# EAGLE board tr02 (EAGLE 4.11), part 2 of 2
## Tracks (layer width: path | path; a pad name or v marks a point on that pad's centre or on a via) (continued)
BAC02  (via drill 0.61) (continued)
  Bottom 0.127: B07.F1 226.68,48.09 226.05,48.73 226.05,53.18 225.41,53.81 225.41,66.51 227,68.1 227,76.35 225.73,77.62 225.73,115.72 226.68,116.67 A07.F1 | v304.15,48.73 304.79,49.37 304.79,64.29 305.42,64.92 305.42,81.11 304.79,81.75 304.79,117.94 305.1,118.26 | 305.1,118.26 306.06,119.21 306.06,119.85 A01.E1 | v260.65,117.63 263.51,120.48 263.51,132.55 268.27,137.31 305.1,137.31 305.1,118.26
BAC03
  Bottom 0.127: B01.H1 306.06,44.92 305.1,45.87 305.1,63.97 305.74,64.6 305.74,81.43 305.1,82.07 305.1,112.55 306.06,113.5 A01.H1
BAC04  (via drill 0.61)
  Top 0.127: 299.07,112.55 301.29,112.55 302.56,111.28 A01.J1 | 299.07,112.55 236.52,112.55 234.94,114.13 233.67,114.13 232.4,112.86 229.22,112.86 227.63,111.28 A07.J1 | B07.J1 227.63,40.79 229.22,39.2 232.4,39.2 235.25,36.35 243.51,36.35 244.14,36.98 273.99,36.98 274.62,36.35 300.02,36.35 302.88,39.2 302.88,40.48 B01.J1 | v299.07,112.86 299.07,112.55
  Bottom 0.127: v299.07,112.86 298.75,113.18 298.75,114.45 299.71,115.4 301.61,115.4 301.61,43.02 302.88,41.74 B01.J1
BAC05  (via drill 0.61)
  Top 0.127: B07.L1 227.63,35.08 228.59,36.03 v262.24,36.03 301.61,36.03 302.56,35.08 B01.L1 | v229.86,104.93 227.63,104.93 A07.L1 | v230.81,116.99 232.4,118.58 v262.88,118.58 v304.15,118.58
  Bottom 0.127: v229.86,104.93 231.44,106.52 231.44,116.36 v230.81,116.99 | v304.15,118.58 304.47,118.26 304.47,106.2 303.51,105.24 A01.L1 | v262.24,36.03 261.92,36.35 261.92,80.8 263.51,82.38 263.51,117.94 v262.88,118.58
BAC06  (via drill 0.61)
  Top 0.127: 222.55,33.17 222.55,31.27 223.51,30.32 224.78,30.32 226.36,28.73 B07.N1 | 222.55,33.17 297.48,33.17 298.12,33.81 302.56,33.81 304.47,31.9 305.74,31.9 B01.M1 | v221.6,95.08 222.87,96.35 224.78,96.35 226.36,97.94 A07.N1 227.63,98.58 228.59,99.53 241.92,99.53 v242.56,98.89 | 222.55,33.17 v221.28,33.17 | v247.64,103.97 249.54,105.88 290.81,105.88 291.45,105.24 293.67,105.24 294.31,105.88 306.06,105.88 306.06,102.07 A01.M1
  Bottom 0.127: v221.6,95.08 222.24,94.45 222.24,57.62 220.65,56.03 220.65,55.4 221.92,54.13 221.92,33.81 v221.28,33.17 | v242.56,98.89 v247.64,103.97
BAC07  (via drill 0.61)
  Top 0.127: 249.86,23.65 304.47,23.65 305.74,24.92 B01.P1 | 249.86,23.65 228.9,23.65 227.63,22.38 B07.R1 | v227.32,89.37 227.95,90 243.51,90 | v245.1,88.42 243.51,90 | v249.86,23.01 249.86,23.65 | v262.56,97.31 262.88,96.99 304.15,96.99 305.74,95.4 A01.P1 | v260.34,86.19 259.38,87.15 254.3,87.15 251.45,90 243.51,90
  Bottom 0.127: v227.32,89.37 227.32,91.27 A07.R1 | v245.1,88.42 244.46,87.78 244.46,36.03 249.86,30.63 v249.86,23.01 | v262.56,97.31 260.34,95.08 v260.34,86.19
BAC08  (via drill 0.61)
  Top 0.127: B01.S1 305.74,18.57 304.15,16.98 299.71,16.98 290.81,8.09 228.59,8.09 227.63,9.04 B07.V1 | v303.83,89.69 305.1,89.69 305.74,89.05 A01.S1
  Bottom 0.127: B07.V1 227.32,10 228.27,10.95 228.27,77.62 227.32,78.57 A07.V1 | v303.83,89.69 304.47,89.05 304.47,50.32 301.93,47.78 301.93,43.97 304.47,41.43 304.47,21.11 306.06,19.52 B01.S1
BAC09  (via drill 0.61)
  Top 0.127: B07.E2 224.14,51.27 224.14,55.08 230.49,55.08 233.03,52.54 295.26,52.54 296.21,53.49 B01.D2 | v224.46,117.31 226.05,115.72 303.2,115.72 305.1,117.63 305.1,119.53 300.66,119.53 300.34,119.21 299.71,119.21 297.17,121.75 297.17,123.02 A01.D2
  Bottom 0.127: v224.46,117.31 224.46,119.53 224.14,119.85 A07.E2 | B01.D2 297.17,54.45 298.12,55.4 298.12,122.07 297.17,123.02 A01.D2
BAC10  (via drill 0.61)
  Top 0.127: v225.09,51.91 298.44,51.91 299.39,50.95 B01.E2 | A01.E2 300.66,120.17 300.98,119.85 305.42,119.85 305.42,115.4 264.78,115.4 262.24,112.86 239.38,112.86 236.84,115.4 225.41,115.4 224.46,114.45 A07.H2
  Bottom 0.127: B07.H2 224.14,44.92 225.09,45.87 v225.09,51.91 225.09,112.55 224.14,113.5 A07.H2
BAC11  (via drill 0.61)
  Top 0.127: v299.39,35.08 298.75,35.08 297.17,33.49 224.14,33.49 224.14,37.3 B07.K2
  Bottom 0.127: B07.K2 223.51,38.57 222.55,39.52 222.55,106.2 223.51,107.15 A07.K2 | 301.29,45.87 300.34,44.92 B01.H2 | 301.29,45.87 301.29,112.55 300.34,113.5 A01.H2 | v299.39,35.08 301.29,36.98 301.29,45.87
BIOP1  (via drill 0.61)
  Top 0.127: v237.79,39.2 298.44,39.2 299.39,38.25 B01.K2
  Bottom 0.127: B06.P2 236.84,25.87 237.79,26.82 v237.79,39.2 237.79,93.5 236.84,94.45 A06.P2 | B01.K2 299.71,38.57 298.75,39.52 298.75,101.75 300.02,103.02 300.02,107.15 A01.K2
BIOP2  (via drill 0.61)
  Top 0.127: B01.M2 299.39,31.27 297.8,29.68 293.36,29.68 290.18,26.51 233.03,26.51 230.49,23.96 227.32,23.96 225.73,22.38 225.73,21.11 226.36,21.11 226.68,20.79 231.76,20.79 232.71,21.74 B06.R2 | v247.64,97.31 247.95,96.99 259.06,96.99 261.61,99.53 297.8,99.53 299.39,101.12 A01.M2 | v246.37,93.5 247.32,92.54 247.32,90.64 234.94,90.64 233.98,91.59 A06.R2
  Bottom 0.127: B06.R2 233.03,22.7 232.08,23.65 232.08,62.06 233.35,63.34 233.35,77.62 232.08,78.89 232.08,90.32 233.03,91.27 A06.R2 | v247.64,97.31 246.37,96.04 v246.37,93.5
BIOP4  (via drill 0.61)
  Top 0.127: A06.S2 237.16,88.42 238.43,87.15 v239.7,87.15 240.02,87.46 251.45,87.46 v252.08,88.1 | v253.67,89.69 254.3,90.32 271.45,90.32 272.08,90.96 277.16,90.96 277.48,90.64 285.42,90.64 285.42,94.77 287,96.35 298.44,96.35 299.39,95.4 A01.P2
  Bottom 0.127: 240.97,7.14 301.29,7.14 301.29,23.65 300.34,24.6 B01.P2 | 240.97,7.14 240.33,7.14 235.25,12.22 235.25,17.3 236.21,18.25 B06.S2 | v239.7,87.15 240.97,85.88 240.97,51.59 239.7,50.32 239.7,49.05 240.97,47.78 240.97,7.14 | v252.08,88.1 v253.67,89.69
BMB00H
  Bottom 0.127: B02.B1 290.81,60.8 291.77,61.75 291.77,128.42 290.81,129.38 A02.B1
BMB01H  (via drill 0.61)
  Top 0.127: v290.18,58.57 v281.29,67.46 | v281.29,78.57 283.51,80.8 v284.47,80.8 | v282.88,119.53 286.69,123.34 289.86,123.34 A02.D1
  Bottom 0.127: v290.18,58.57 290.18,54.45 B02.D1 | v281.29,67.46 v281.29,78.57 | v284.47,80.8 282.88,82.38 v282.88,119.53
BMB02H  (via drill 0.61)
  Top 0.127: v260.34,50.63 261.61,49.37 292.09,49.37 293.04,50.32 B02.E1 | v255.57,128.42 v271.76,128.42
  Bottom 0.127: v260.34,50.63 257.16,53.81 257.16,110.96 254.3,113.82 254.3,127.15 v255.57,128.42 | v271.76,128.42 278.12,134.77 292.4,134.77 292.4,122.07 293.36,121.12 A02.E1
BMB03H  (via drill 0.61)
  Top 0.127: 238.75,55.4 236.52,55.4 235.89,56.03 235.25,56.03 233.67,54.45 B06.D2 | 238.75,55.4 v291.13,55.4 | 238.75,55.4 v238.75,56.03 | v288.91,132.55 288.28,131.92 241.29,131.92 v240.65,132.55
  Bottom 0.127: v291.13,55.4 291.77,54.76 291.77,42.7 290.81,41.74 B02.J1 | 237.79,128.11 235.25,128.11 233.98,126.83 233.98,124.61 233.67,124.29 A06.D2 | 237.79,128.11 237.79,105.24 237.16,104.61 237.16,103.66 238.11,102.7 238.11,56.67 v238.75,56.03 | v288.91,132.55 288.91,112.86 290.18,111.59 A02.J1 | v240.65,132.55 237.79,129.69 237.79,128.11
BMB03L
  Bottom 0.127: B02.H1 293.36,44.92 292.4,45.87 292.4,77.3 293.67,78.57 293.67,80.8 292.4,82.07 292.4,112.55 293.36,113.5 A02.H1
BMB04H  (via drill 0.61)
  Top 0.127: v240.65,50 237.48,50 237.16,50.32 B06.E2 | v241.29,120.48 237.16,120.48 A06.E2 | v248.91,30.32 292.09,30.32 293.04,31.27 B02.M1 | v247,106.2 v293.36,106.2
  Bottom 0.127: 241.29,50.63 v240.65,50 | 241.29,117.31 v241.29,120.48 | 241.29,50.63 241.29,117.31 | v248.91,30.32 241.29,37.94 241.29,50.63 | v293.36,106.2 293.36,102.07 A02.M1 | v247,106.2 244.14,109.05 244.14,114.45 241.29,117.31
BMB04L
  Bottom 0.127: B02.L1 290.18,35.4 289.23,36.35 289.23,103.02 290.18,103.97 A02.L1
BMB05H  (via drill 0.61)
  Top 0.127: v287.96,41.11 280.34,48.73 234.94,48.73 233.98,47.78 B06.F2 | v233.98,113.18 234.94,112.23 288.91,112.23 | 288.91,112.23 290.81,112.23 v293.67,109.37 | v295.9,89.37 295.58,89.05 294.31,89.05 A02.S1 | v288.91,111.59 288.91,112.23
  Bottom 0.127: B02.S1 293.36,19.52 293.36,20.79 288.91,25.23 288.91,40.16 v287.96,41.11 288.28,41.43 288.91,42.06 v288.91,111.59 | v233.98,113.18 233.98,116.36 233.67,116.67 A06.F2 | v293.67,109.37 295.58,107.47 295.58,89.69 v295.9,89.37
BMB05L
  Bottom 0.127: B02.P1 293.99,25.87 294.94,26.82 294.94,93.5 293.99,94.45 A02.P1
BMB06H  (via drill 0.61)
  Top 0.127: v286.69,41.11 281.61,46.19 267.64,46.19 v266.05,47.78 | v266.05,56.35 266.37,56.67 v272.4,56.67
  Bottom 0.127: v286.69,41.11 286.05,41.74 286.05,49.05 287,50 B02.E2 | v266.05,47.78 v266.05,56.35 | v272.4,56.67 273.04,57.3 273.04,117.31 276.21,120.48 276.21,131.6 279.7,131.6 279.7,126.52 280.97,125.25 287,125.25 287,121.12 A02.E2
BMB06L  (via drill 0.61)
  Top 0.127: v235.57,55.08 282.56,55.08 283.51,54.13 B02.D2
  Bottom 0.127: 235.25,55.08 235.25,78.89 236.52,80.16 236.52,80.8 235.25,82.07 235.25,112.55 236.21,113.5 A06.H2 | 235.25,55.08 235.25,45.87 236.21,44.92 B06.H2 | B02.D2 284.47,54.45 285.42,55.4 285.42,122.07 284.47,123.02 A02.D2 | 235.25,55.08 v235.57,55.08
BMB07H
  Bottom 0.127: B02.K2 287,38.57 285.74,39.84 285.74,52.22 286.05,52.54 286.05,106.2 287,107.15 A02.K2
BMB07L
  Top 0.127: B06.J2 233.98,40.79 234.62,40.16 239.06,40.16 239.38,39.84 287.96,39.84 288.91,40.79 288.91,43.65 287.64,43.65 B02.H2
  Bottom 0.127: A06.J2 233.67,110.32 234.62,109.37 234.62,42.7 233.67,41.74 B06.J2 | A02.H2 287.64,113.5 287.96,113.18 287.96,108.74 288.59,108.1 288.59,45.87 287.64,44.92 B02.H2
BMB08H  (via drill 0.61)
  Top 0.127: v234.94,25.23 236.21,23.96 254.94,23.96 255.57,24.6 273.67,24.6 274.31,23.96 285.74,23.96 286.69,24.92 B02.P2 287.96,25.55 290.5,25.55 v292.09,27.14 | v291.45,57.94 291.77,57.94 291.77,70 304.47,82.7 304.47,87.78 301.61,90.64 287.64,90.64 287.64,94.45 A02.P2
  Bottom 0.127: v234.94,25.23 234.94,36.03 236.21,37.3 B06.K2 | v291.45,57.94 292.09,57.3 v292.09,27.14
BMB08L  (via drill 0.61)
  Top 0.127: v298.44,32.86 288.91,32.86 287.96,31.9 B02.M2 | v299.07,103.34 298.44,102.7 288.91,102.7 287.96,101.75 A02.M2 286.69,101.12 285.42,99.85 259.38,99.85 259.06,100.16 239.38,100.16 v236.52,103.02
  Bottom 0.127: v298.44,32.86 298.44,102.7 v299.07,103.34 | v236.52,103.02 236.52,107.15 A06.K2
BMB09H  (via drill 0.61)
  Top 0.127: v285.42,27.46 285.1,27.14 256.84,27.14 | 256.84,27.14 229.86,27.14 225.73,31.27 224.46,31.27 B07.M2 | v287,86.51 284.47,83.97 v256.21,83.97 | 256.84,27.14 v256.84,27.46 | v255.57,103.02 238.11,103.02 237.16,103.97 236.21,103.97 234.94,102.7 229.86,102.7 228.9,101.75 224.46,101.75 A07.M2
  Bottom 0.127: v285.42,27.46 285.42,21.11 287,19.52 B02.S2 | v287,86.51 287,88.1 A02.S2 | 256.84,83.34 v256.21,83.97 | v256.84,27.46 256.84,83.34 | v255.57,103.02 256.84,101.75 256.84,83.34
BMB10H  (via drill 0.61)
  Top 0.127: v225.73,19.2 227.32,17.62 230.81,17.62 231.12,17.93 235.89,17.93 236.52,17.3 282.24,17.3 283.51,16.03 B02.T2 | 251.76,90.32 253.99,88.1 254.62,88.1 255.26,87.46 257.8,87.46 258.43,88.1 259.7,88.1 260.97,86.83 282.56,86.83 283.51,85.88 A02.T2 | 251.76,90.32 247.64,94.45 246.05,94.45 245.1,93.5 225.73,93.5 224.46,94.77 A07.P2 | v219.06,87.78 221.6,90.32 251.76,90.32
  Bottom 0.127: v225.73,19.2 225.73,20.79 | 225.73,20.79 225.73,23.01 224.14,24.6 B07.P2 | 225.73,20.79 219.06,20.79 v219.06,87.78
BMB11H  (via drill 0.61)
  Top 0.127: B07.S2 224.46,18.57 226.05,16.98 274.94,16.98 282.24,9.68 283.51,9.68 B02.V2 | v231.12,87.15 225.73,87.15 224.46,88.42 A07.S2 | v231.76,73.18 232.4,73.81 288.28,73.81 293.67,79.21 293.67,80.48 285.74,80.48 284.78,79.53 A02.V2
  Bottom 0.127: A02.V2 283.83,78.57 282.88,77.62 282.88,10.95 283.83,10 B02.V2 | v231.12,87.15 231.76,86.51 v231.76,73.18
CLEAR_AC_L  (via drill 0.61)
  Top 0.127: v270.5,25.55 273.99,25.55 B03.P2 | v269.23,91.27 272.72,94.77 273.99,94.77 A03.P2 | v267.64,122.07 254.3,122.07 253.03,123.34 A05.D1
  Bottom 0.127: v270.5,25.55 269.86,26.19 269.86,90.64 | 269.86,90.64 v269.23,91.27 | v267.64,122.07 267,121.44 267,104.29 269.86,101.43 269.86,90.64
GND  (via drill 0.61)  (1 unrouted)
  Top 0.203: C3.2 148.26,167.16 145.08,167.16 140,162.08 R4.1 138.73,162.08 137.46,160.81 133.65,160.81 131.11,158.27 S4.2 | B03.R2 272.08,21.74 277.16,21.74 B03.R1 278.43,21.74 283.51,21.74 B02.R2 | B03.F1 277.16,47.14 272.08,47.14 B03.F2 | B02.N1 289.86,28.41 284.78,28.41 B02.N2 | B02.F2 284.78,47.14 289.86,47.14 B02.F1 291.13,47.14 296.21,47.14 B01.F2 | B02.K1 293.04,37.62 292.09,36.66 282.56,36.66 281.61,37.62 B03.K1 | B03.C1 280.34,56.67 275.26,56.67 B03.C2 273.99,57.3 273.04,58.26 234.94,58.26 | B03.A1 280.66,62.7 280.66,57.62 B03.C1 | B03.C1 281.61,56.67 286.69,56.67 B02.C2 287.96,56.67 293.04,56.67 B02.C1 | B02.A1 293.36,62.7 293.36,57.62 B02.C1 | B02.C1 294.31,56.67 299.39,56.67 B01.C2 300.66,56.67 304.47,56.67 | 304.47,56.67 305.74,56.67 B01.C1 306.06,57.62 306.06,62.7 B01.A1 | B01.U2 300.66,12.85 302.88,15.08 B01.T1 | B02.U2 287.96,12.85 290.18,15.08 B02.T1 | B01.R2 296.21,21.74 291.13,21.74 B02.R1 | 296.53,42.38 296.53,41.74 B01.J2 | 296.53,42.38 296.53,46.83 B01.F2 | 301.29,47.14 297.48,47.14 B01.F2 | 301.29,47.14 302.56,47.14 B01.F1 | 296.53,42.38 306.06,42.38 306.06,38.57 B01.K1 | B01.N1 302.56,28.09 297.48,28.09 B01.N2 | 304.47,56.67 304.47,49.68 303.83,49.68 301.29,47.14 | B18.T1 87.93,15.39 88.89,14.44 123.81,14.44 124.76,15.39 B15.T1 126.03,15.39 126.98,14.44 177.79,14.44 | 177.79,14.44 176.83,15.39 B11.T1 | 200.01,14.44 177.79,14.44 | 200.01,14.44 200.96,15.39 B09.T1 | 212.71,14.44 213.66,15.39 B08.T1 | 212.71,14.44 200.01,14.44 | 225.41,14.44 226.36,15.39 B07.T1 | 225.41,14.44 212.71,14.44 | 238.11,14.44 239.06,15.39 B06.T1 | 238.11,14.44 225.41,14.44 | 238.11,14.44 272.4,14.44 273.99,12.85 B03.U2
  Top 0.203: 57.13,125.56 47.61,125.56 46.66,126.52 A21.C2 45.39,127.15 44.44,128.11 34.91,128.11 33.96,127.15 A22.C2 32.69,126.52 27.61,126.52 A23.C1 26.34,126.52 21.26,126.52 A23.C2 19.99,126.52 14.91,126.52 A24.C1 13.64,126.52 8.56,126.52 A24.C2 | 57.13,125.56 58.09,126.52 A20.C2 | 69.83,125.56 70.79,126.52 A19.C2 | 69.83,125.56 57.13,125.56 | 82.53,125.56 83.49,126.52 A18.C2 | 82.53,125.56 69.83,125.56 | 95.23,125.56 96.19,126.52 A17.C2 | 95.23,125.56 82.53,125.56 | 107.94,125.56 108.89,126.52 A16.C2 | 107.94,125.56 95.23,125.56 | 120.64,125.56 121.59,126.52 A15.C2 | 120.64,125.56 107.94,125.56 | 120.64,125.56 133.34,125.56 134.29,126.52 A14.C2 135.56,126.52 140.64,126.52 A14.C1 141.91,126.83 146.99,126.83 A13.C2 148.26,126.52 149.53,125.25 158.42,125.25 159.69,126.52 A12.C2 160.96,126.52 161.91,125.56 171.44,125.56 | B24.C2 8.56,56.67 13.64,56.67 B24.C1 14.91,56.67 19.99,56.67 B23.C2 21.26,56.67 26.34,56.67 B23.C1 | 15.86,36.03 16.81,35.08 B23.L2 | 15.86,36.03 14.59,37.3 B24.K1 14.91,38.25 17.13,40.48 B23.J2 | B23.F1 23.16,47.14 18.08,47.14 B23.F2 | 15.86,36.03 24.75,36.03 26.34,37.62 B23.K1 | B23.U2 21.26,12.85 23.48,15.08 B23.T1 23.48,16.35 23.48,21.43 B23.R1 | B24.U2 8.56,12.85 10.78,15.08 B24.T1 10.78,16.35 10.78,21.43 B24.R1 | B24.R2 5.38,21.74 10.46,21.74 B24.R1 | B24.N2 4.43,29.05 4.43,34.12 B24.L2 4.43,35.4 4.43,40.48 B24.J2 | B23.R2 16.81,21.74 11.73,21.74 B24.R1 | B24.F1 10.46,47.14 5.38,47.14 B24.F2 | B23.N1 23.16,28.09 18.08,28.09 B23.N2 | 22.53,83.97 23.48,84.92 A23.T1 | 22.53,83.97 21.26,82.7 A23.U2 | 22.53,83.97 v34.59,83.97 34.91,83.97 47.29,83.97 47.61,84.29
  Top 0.203: 47.61,84.29 48.56,85.24 A21.T1 | 47.61,84.29 60.31,84.29 61.26,85.24 A20.T1 | A24.U2 8.56,82.7 10.78,84.92 A24.T1 | A23.R2 16.81,91.59 11.73,91.59 A24.R1 10.46,91.59 5.38,91.59 A24.R2 4.43,92.54 4.43,97.62 A24.N2 | A24.J2 4.43,111.59 4.43,116.67 A24.F2 5.38,116.99 10.46,116.99 A24.F1 | A23.F1 23.16,116.99 18.08,116.99 A23.F2 | A23.N1 23.16,97.94 18.08,97.94 A23.N2 | 85.71,84.29 76.19,84.29 75.23,85.24 A19.T1 | 85.71,84.29 86.66,85.24 A18.T1 | 98.41,84.29 99.36,85.24 A17.T1 | 98.41,84.29 85.71,84.29 | 98.41,84.29 111.11,84.29 112.06,85.24 A16.T1 113.33,85.24 114.28,84.29 120.95,84.29 122.22,85.56 124.76,85.56 A15.T1 126.03,85.24 131.11,85.24 A14.T2 132.38,85.24 137.46,85.24 A14.T1 138.73,85.24 139.69,84.29 149.21,84.29 | 149.21,84.29 150.16,85.24 A13.T1 | 161.91,84.29 162.86,85.24 A12.T1 | 161.91,84.29 149.21,84.29 | 174.61,84.29 175.56,85.24 A11.T1 | 174.61,84.29 161.91,84.29 | 174.61,84.29 187.31,84.29 188.26,85.24 A10.T1 189.53,85.88 190.49,86.83 200.01,86.83 200.96,85.88 A09.T1 202.23,85.88 203.5,87.15 209.22,87.15 210.49,85.88 213.66,85.88 A08.T1 214.93,85.88 215.89,86.83 225.41,86.83 226.36,85.88 A07.T1 227.63,85.88 227.95,86.19 232.08,86.19 232.71,86.83 238.11,86.83 239.06,85.88 A06.T1 240.33,85.88 241.29,86.83 250.81,86.83 251.76,85.88 A05.T1 253.03,85.24 258.11,85.24 A04.T2 259.38,85.24 264.46,85.24 A04.T1 | 171.44,125.56 172.39,126.52 A11.C2 | 184.14,125.56 185.09,126.52 A10.C2 | 171.44,125.56 184.14,125.56 | 184.14,125.56 196.84,125.56 197.79,126.52 A09.C2 199.06,127.15 200.01,128.11 209.54,128.11 210.49,127.15 A08.C2 211.76,126.52 213.66,126.52 214.62,125.56 222.24,125.56
  Top 0.203: 222.24,125.56 223.19,126.52 A07.C2 | 235.57,125.56 236.21,126.2 A06.C2 | 222.24,125.56 235.57,125.56 | 235.57,125.56 247.64,125.56 248.59,126.52 A05.C2 249.86,127.15 252.08,129.38 A05.B1 252.72,129.38 254.94,127.15 A05.C1 256.21,126.52 261.29,126.52 A04.C2 262.56,126.52 263.51,125.56 273.04,125.56 273.99,126.52 A03.C2 275.26,126.52 280.34,126.52 A03.C1 281.61,126.52 286.69,126.52 A02.C2 287.96,126.52 293.04,126.52 A02.C1 294.31,126.52 299.39,126.52 A01.C2 300.66,126.52 305.74,126.52 A01.C1 306.06,127.47 306.06,132.55 A01.A1 | A03.K1 281.61,107.47 282.56,106.52 292.09,106.52 293.04,107.47 A02.K1 294.31,108.1 295.9,109.69 | 295.9,109.69 296.53,110.32 A01.J2 | A01.F1 302.56,116.99 297.48,116.99 A01.F2 296.21,116.99 291.13,116.99 A02.F1 289.86,116.99 284.78,116.99 A02.F2 | 295.9,109.69 304.15,109.69 305.74,108.1 A01.K1 | A03.R2 272.08,91.59 277.16,91.59 A03.R1 278.43,91.59 283.51,91.59 A02.R2 | A03.F1 277.16,116.99 272.08,116.99 A03.F2 | 234.94,58.26 225.41,58.26 224.46,57.3 B07.C2 223.19,57.3 222.24,58.26 214.62,58.26 213.35,56.98 211.76,56.98 B08.C2 210.49,57.3 209.54,58.26 196.84,58.26 | 234.94,58.26 235.89,57.3 B06.C2 | 196.84,58.26 174.61,58.26 173.66,57.3 B11.C2 | 196.84,58.26 197.79,57.3 B09.C2 | A05.V1 253.03,79.53 255.26,81.75 A05.U1 256.21,82.7 257.16,83.65 266.69,83.65 267.64,82.7 A04.U1 268.91,82.07 273.99,82.07 A03.U2 275.26,82.7 276.21,83.65 288.91,83.65 | A01.U2 300.66,82.7 302.88,84.92 A01.T1 | 288.91,83.65 290.18,84.92 A02.T1 | 288.91,83.65 287.96,82.7 A02.U2 | A01.R2 296.21,91.59 291.13,91.59 A02.R1 | A01.N1 302.56,97.94 297.48,97.94 A01.N2
  Bottom 0.203: S3.2 148.89,158.9 148.89,166.52 C3.2 | B03.U2 275.26,12.85 277.48,15.08 B03.T1 277.48,16.35 277.48,21.43 B03.R1 277.48,22.7 277.48,27.78 B03.N1 278.12,29.05 279.07,30 279.07,35.71 280.66,37.3 B03.K1 | B03.R2 271.45,22.7 271.45,27.78 B03.N2 271.13,29.05 271.13,34.12 B03.L2 271.13,35.4 271.13,40.48 B03.J2 271.13,41.74 271.13,46.83 B03.F2 | B02.R2 283.83,22.7 283.83,27.78 B02.N2 283.83,29.05 283.83,34.12 B02.L2 283.83,35.4 283.83,40.48 B02.J2 283.83,41.74 283.83,46.83 B02.F2 | B01.T1 302.88,16.35 302.88,21.43 B01.R1 302.88,22.7 302.88,27.78 B01.N1 | B02.R1 290.18,21.43 290.18,16.35 B02.T1 | B01.R2 296.53,22.7 296.53,27.78 B01.N2 296.53,29.05 296.53,34.12 B01.L2 296.53,35.4 296.53,40.48 B01.J2 | A14.M2 135.24,102.07 136.83,103.66 136.83,109.37 137.78,110.32 A14.J1 137.78,111.59 136.19,113.18 136.19,118.9 135.24,119.85 A14.E2 134.61,121.12 134.61,126.2 A14.C2 | B24.A1 13.96,62.7 13.96,57.62 B24.C1 13.96,56.35 12.37,54.76 12.37,49.05 11.41,48.09 B24.F1 | B23.C1 26.66,57.62 26.66,62.7 B23.A1 26.66,63.97 25.38,65.24 25.38,83.65 24.11,84.92 A23.T1 23.48,86.19 23.48,91.27 A23.R1 23.48,92.54 23.48,97.62 A23.N1 | B23.F2 17.13,46.83 17.13,41.74 B23.J2 | B23.N1 23.48,27.78 23.48,22.7 B23.R1 | B24.N2 4.43,27.78 4.43,22.7 B24.R2 | B24.N1 10.78,27.78 10.78,22.7 B24.R1 | B23.R2 17.13,22.7 17.13,27.78 B23.N2 17.13,29.05 17.13,34.12 B23.L2 | B24.F2 4.43,46.83 4.43,41.74 B24.J2 | v34.59,83.97 35.86,85.24 A22.T1 | A24.A1 13.96,132.55 13.96,127.47 A24.C1 | A23.A1 26.66,132.55 26.66,127.47 A23.C1 26.66,126.2 25.07,124.61 25.07,115.72 | 25.07,115.72 25.07,110.01 26.66,108.42 A23.K1
  Bottom 0.203: 25.07,115.72 24.11,116.67 A23.F1 | A24.K1 13.96,108.42 12.37,110.01 12.37,115.72 11.41,116.67 A24.F1 | A24.N1 10.78,97.62 10.78,92.54 A24.R1 10.78,91.27 10.78,86.19 A24.T1 | A23.R2 17.13,92.54 17.13,97.62 A23.N2 17.13,98.89 17.13,103.97 A23.L2 17.13,105.24 17.13,110.32 A23.J2 17.13,111.59 17.13,116.67 A23.F2 | A24.N2 4.43,98.89 4.43,103.97 A24.L2 4.43,105.24 4.43,110.32 A24.J2 | B15.C2 121.59,57.3 114.28,57.3 114.28,79.53 113.02,80.8 113.02,84.92 A16.T1 | B18.C2 84.44,57.62 86.03,59.21 86.03,83.97 86.98,84.92 A18.T1 | A14.P1 140.96,94.45 139.37,92.86 139.37,87.15 138.42,86.19 A14.T1 | A04.L2 258.43,105.24 257.48,106.2 257.48,111.91 255.89,113.5 A05.H1 255.89,114.77 256.84,115.72 256.84,125.25 255.89,126.2 A05.C1 | A03.A1 280.66,132.55 280.66,127.47 A03.C1 | A02.A1 293.36,132.55 293.36,127.47 A02.C1 293.99,126.2 295.58,124.61 295.58,118.9 296.53,117.94 A01.F2 296.53,116.67 296.53,111.59 A01.J2 296.53,110.32 296.53,105.24 A01.L2 296.53,103.97 296.53,98.89 A01.N2 296.53,97.62 296.53,92.54 A01.R2 | A03.T1 277.8,86.19 277.8,91.27 A03.R1 277.48,92.54 277.48,97.62 A03.N1 | A03.R2 271.13,92.54 271.13,97.62 A03.N2 271.13,98.89 271.13,103.97 A03.L2 271.13,105.24 271.13,110.32 A03.J2 271.13,111.59 271.13,116.67 A03.F2 | A02.R2 283.83,92.54 283.83,97.62 A02.N2 283.83,98.89 283.83,103.97 A02.L2 283.83,105.24 283.83,110.32 A02.J2 283.83,111.59 283.83,116.67 A02.F2 | A04.V1 264.78,79.84 264.78,84.92 A04.T1 | A05.U1 254.94,82.7 252.72,84.92 A05.T1 | A01.T1 302.88,86.19 302.88,91.27 A01.R1 302.88,92.54 302.88,97.62 A01.N1 | A02.T1 290.18,86.19 290.18,91.27 A02.R1 290.18,92.54 290.18,97.62 A02.N1
  Bottom 0.203: B08.C2 211.44,57.62 211.76,57.94 211.76,62.06 213.03,63.34 213.03,83.97 213.98,84.92 A08.T1
I_LINE
  Bottom 0.127: B03.V2 271.13,10 270.18,10.95 270.18,19.2 272.72,21.74 272.72,50.95 270.18,53.49 270.18,75.4 271.13,76.35 271.13,78.57 A03.V2
I_RUN  (via drill 0.61)
  Top 0.127: v267,59.21 280.34,72.54 292.09,72.54 298.75,79.21 298.75,87.46 300.34,87.46 301.29,88.42 301.29,90.32 278.43,90.32 277.16,89.05 275.26,89.05 A03.S2
  Bottom 0.127: v267,59.21 267,7.77 272.08,7.77 273.04,8.73 273.04,16.98 274.31,18.25 B03.S2
I_TS1  (via drill 0.61)
  Top 0.127: v264.46,20.79 296.53,20.79 296.53,16.35 B01.T2 | v262.88,78.57 263.51,77.94 279.38,77.94 283.19,81.75 286.37,81.75 287,81.11 290.81,81.11 294.94,85.24 296.21,85.24 A01.T2
  Bottom 0.127: v264.46,20.79 263.19,22.06 263.19,78.26 v262.88,78.57
I_TS3  (via drill 0.61)
  Top 0.127: v265.1,72.22 266.37,73.49 289.23,73.49 298.44,82.7 298.44,88.42 299.39,88.42 A01.S2
  Bottom 0.127: v265.1,72.22 265.1,47.46 265.42,47.14 265.42,7.46 296.53,7.46 298.12,9.04 298.12,16.66 299.71,18.25 B01.S2
I_TT_INST  (via drill 0.61)
  Top 0.127: v268.59,84.92 268.91,85.24 270.81,85.24 A03.T2
  Bottom 0.127: v268.59,84.92 266.05,82.38 266.05,81.11 267.96,79.21 267.96,8.09 271.76,8.09 272.72,9.04 272.72,14.12 271.76,15.08 B03.T2
INITIALIZE  (via drill 0.61)
  Top 0.127: v243.51,71.27 265.42,71.27 267,72.86 290.18,72.86 296.21,78.89 A01.V2
  Bottom 0.127: B01.V2 296.53,10 295.58,10.95 295.58,77.62 296.53,78.57 A01.V2 | 244.14,71.27 244.14,96.04 241.6,98.58 241.6,112.55 242.56,113.5 A06.H1 | 244.14,71.27 244.14,45.87 243.19,44.92 B06.H1 | 244.14,71.27 v243.51,71.27
INT_REQ_L  (via drill 0.61)
  Top 0.127: v262.24,32.22 273.67,32.22 273.99,31.9 B03.M2 | v259.7,100.8 260.34,100.16 273.04,100.16 273.99,101.12 A03.M2
  Bottom 0.127: v262.24,32.22 261.29,33.17 261.29,76.35 259.06,78.57 A04.V2 258.43,79.84 257.48,80.8 257.48,98.58 v259.7,100.8
N$1
  Bottom 0.127: B07.C1 229.86,56.35 228.9,55.4 228.9,15.39 233.03,11.27 233.03,10 B06.V2
N$2
  Top 0.127: B11.S1 180.01,19.2 180.96,20.16 209.54,20.16 210.49,19.2 B08.S2
N$3
  Top 0.127: B11.C1 180.01,56.67 181.6,55.08 214.62,55.08 216.52,53.18 216.52,51.27 211.44,51.27 B08.E2
  Bottom 0.127: B08.E2 211.44,50 212.71,48.73 212.71,11.27 213.98,10 B08.V1
N$4  (via drill 0.61)
  Top 0.127: v95.55,111.91 95.87,111.59 99.05,111.59 99.68,112.23 113.02,112.23 v114.92,110.32
  Bottom 0.127: v95.55,111.91 95.55,121.44 93.97,123.02 A17.D2 | v114.92,110.32 114.28,109.69 114.28,103.34 115.55,102.07 A16.M1
N$5  (via drill 0.61)
  Top 0.127: v110.16,118.58 92.69,118.58 91.11,120.17 A18.E1
  Bottom 0.127: v110.16,118.58 111.11,117.63 111.11,106.52 112.38,105.24 A16.L1
N$6  (via drill 0.61)
  Top 0.127: v96.5,110.32 95.87,109.69 77.45,109.69 73.33,113.82 72.06,113.82 A19.H2 71.11,113.5 68.88,111.28 A19.J2
  Bottom 0.127: A19.K2 70.79,108.1 68.56,110.32 A19.J2 | v96.5,110.32 96.5,108.42 A17.K2
N$7  (via drill 0.61)
  Top 0.127: v235.57,80.48 234.94,80.48 233.98,79.53 A06.V2 | v234.94,126.52 230.81,126.52 A07.C1
  Bottom 0.127: v235.57,80.48 234.94,81.11 v234.94,126.52
N$8
  Top 0.127: A11.S1 180.01,89.05 180.96,90 209.54,90 210.49,89.05 A08.S2
N$9  (via drill 0.61)
  Top 0.127: v211.44,80.16 213.03,80.16 213.66,79.53 A08.V1 | v209.54,129.38 208.9,128.74 201.28,128.74 200.65,129.38 197.47,129.38 196.2,128.11 180.96,128.11 180.01,127.15 A11.C1
  Bottom 0.127: v211.44,80.16 209.85,81.75 209.85,116.67 211.12,117.94 211.12,119.85 A08.E2 210.81,121.12 210.81,124.29 209.85,125.25 209.85,129.06 v209.54,129.38
N$10  (1 unrouted)
N$11  (via drill 0.61)
  Top 0.127: v164.45,115.09 165.4,116.04 v168.9,116.04
  Bottom 0.127: v164.45,115.09 164.77,114.77 164.77,106.2 163.82,105.24 A12.L1 | v168.9,116.04 168.58,116.36 168.58,122.07 169.53,123.02 A11.D2
N$12  (via drill 0.61)
  Top 0.127: 87.93,106.52 83.17,106.52 v82.53,107.15 | 87.93,106.52 88.89,106.52 89.84,107.47 A18.K1 91.11,107.47 92.06,106.52 161.28,106.52 161.59,106.83 v161.91,107.15 165.72,107.15 166.04,107.47 A12.K1 | 87.93,106.52 v87.93,107.15 | v160.96,123.34 162.86,123.34 A12.D1 | v210.17,118.26 209.54,118.9 v163.5,118.9
  Bottom 0.127: 82.53,97.94 81.58,97.94 A18.N2 | 82.53,97.94 82.85,97.94 85.39,95.4 85.39,94.13 86.98,92.54 A18.R1 | v82.53,107.15 82.53,97.94 | v87.93,107.15 88.57,107.78 88.57,117.63 87.3,118.9 87.3,123.02 A18.D1 | 161.59,107.15 161.59,112.55 160.64,113.5 A12.H2 160.01,114.77 159.05,115.72 159.05,121.44 v160.96,123.34 | 161.59,107.15 161.59,94.13 163.18,92.54 A12.R1 | 161.59,107.15 v161.91,107.15 | v210.17,118.26 209.54,117.63 209.54,81.11 208.27,79.84 A08.V2 | v163.5,118.9 163.5,123.02 A12.D1
N$13  (1 unrouted)
N$14
  Top 0.127: A19.D2 68.56,123.02 70.79,120.8 A19.E2
N$15  (via drill 0.61)
  Top 0.127: v104.44,119.53 104.12,119.21 96.5,119.21 93.97,121.75 83.8,121.75 80.95,118.9 70.15,118.9 68.88,117.63 A19.F2 | v105.08,108.1 108.89,108.1 A16.K2
  Bottom 0.127: v104.44,119.53 105.08,118.9 105.08,114.77 105.71,114.13 105.71,111.91 105.08,111.28 v105.08,108.1
N$16  (via drill 0.61)
  Top 0.127: v91.42,128.11 91.74,128.42 133.65,128.42 v134.29,129.06
  Bottom 0.127: v91.42,128.11 91.74,127.79 91.74,119.53 93.33,117.94 A17.F2 | v134.29,129.06 137.78,125.56 137.78,124.29 A14.D1
N$17  (via drill 0.61)
  Top 0.127: v120.64,99.53 107.94,99.53 106.98,98.58 A16.N2 | v120.64,116.67 121.27,116.04 130.16,116.04 131.11,116.99 A14.F2
  Bottom 0.127: v120.64,99.53 v120.64,116.67
N$18  (via drill 0.61)
  Top 0.127: 194.3,115.72 196.52,115.72 197.79,114.45 A09.H2 | v171.12,115.72 194.3,115.72 | v195.57,96.35 203.19,96.35 204.14,95.4 A09.P1 | 194.3,115.72 v194.3,115.09
  Bottom 0.127: v171.12,115.72 171.12,106.2 170.17,105.24 A11.L2 | v195.57,96.35 193.98,97.94 193.98,112.23 194.3,112.55 v194.3,115.09
N$19  (via drill 0.61)
  Top 0.127: v81.58,99.85 81.9,100.16 107.94,100.16 108.89,101.12 A16.M2
  Bottom 0.127: v81.58,99.85 79.68,101.75 79.68,109.37 80.63,110.32 A18.J2
N$20
  Top 0.127: A13.E1 153.66,119.85 151.43,117.63 A13.F1 | A13.D2 145.08,123.34 150.16,123.34 A13.D1
  Bottom 0.127: A13.F1 151.12,116.67 153.34,114.45 A13.H1 | A13.B1 150.48,129.38 150.48,124.29 A13.D1 151.12,123.02 153.34,120.8 A13.E1
N$21  (via drill 0.61)
  Top 0.127: v121.91,103.66 121.27,103.02 95.55,103.02 94.28,104.29 A17.L2 | v126.67,108.1 126.03,107.47 v124.13,107.47
  Bottom 0.127: A15.N1 125.08,98.89 125.08,100.48 v121.91,103.66 122.22,103.97 122.22,105.56 v124.13,107.47 | v126.67,108.1 126.67,111.91 128.26,113.5 A15.H1
N$22
  Bottom 0.127: A13.C1 153.66,127.47 153.66,132.55 A13.A1
N$23  (via drill 0.61)
  Top 0.127: v98.09,112.55 149.85,112.55 v150.48,113.18 150.8,112.86 168.58,112.86 v168.9,113.18 | v170.17,94.77 172.39,94.77 A11.P2
  Bottom 0.127: v98.09,112.55 98.09,103.02 97.14,102.07 A17.M2 | v150.48,113.18 153.66,110.01 153.66,108.42 A13.K1 | v170.17,94.77 168.26,96.67 168.26,112.55 v168.9,113.18
N$24  (via drill 0.61)
  Top 0.127: v167.94,94.13 167.31,93.5 130.48,93.5 v129.84,94.13
  Bottom 0.127: v167.94,94.13 169.53,92.54 A11.R2 | v129.84,94.13 129.84,106.2 128.89,107.15 A15.K1 127.94,107.47 127.94,107.15 126.35,107.15 125.72,107.78 125.72,110.32 A15.J1
N$25
  Bottom 0.127: A19.V2 67.93,79.84 66.98,80.8 66.98,90.32 67.93,91.27 A19.R2
N$26  (1 unrouted)
N$27  (1 unrouted)
  Bottom 0.127: A19.S2 71.11,89.37 70.15,90.32 70.15,95.4 71.11,96.35 77.45,96.35 77.45,95.72 A19.P1
N$28  (via drill 0.61)
  Top 0.127: v112.06,82.38 107.62,77.94 80.63,77.94 78.09,80.48 68.56,80.48 68.56,84.92 A19.T2
  Bottom 0.127: v112.06,82.38 111.43,83.02 111.43,90.32 112.38,91.27 A16.R1
N$29
  Top 0.127: A15.N2 119.36,97.62 121.59,95.4 A15.P2 122.86,95.4 124.13,95.4 128.26,99.53 149.21,99.53 150.16,98.58 A13.N1
  Bottom 0.127: A16.S1 116.19,88.1 117.46,86.83 117.46,79.21 118.73,77.94 120.32,77.94 120.32,96.67 119.36,97.62 A15.N2
N$30
  Top 0.127: A13.S2 146.99,89.05 144.77,91.27 A13.R2
  Bottom 0.127: A13.V2 145.08,79.53 147.31,81.75 A13.U2 147.31,83.02 147.31,88.1 A13.S2 147.31,89.37 146.35,90.32 146.35,99.85 147.31,100.8 A13.M2
N$31
  Bottom 0.127: A13.V1 151.12,79.84 152.7,81.43 152.7,93.5 153.66,94.45 A13.P1
N$32  (via drill 0.61)
  Top 0.127: v117.14,131.6 105.08,131.6 103.81,132.87 A17.A1 | v187.95,136.68 187.31,137.31 124.76,137.31 123.81,136.36 119.68,136.36 v119.36,136.68
  Bottom 0.127: A16.P1 116.19,95.72 117.14,96.67 117.14,110.64 116.51,111.28 116.51,113.18 117.14,113.82 v117.14,131.6 117.46,131.92 117.46,134.77 v119.36,136.68 | v187.95,136.68 187.95,131.28 188.58,130.65 A10.B1
N$33  (via drill 0.61)
  Top 0.127: v170.48,96.04 173.34,98.89 174.93,98.89 v176.52,100.48
  Bottom 0.127: v170.48,96.04 171.12,95.4 171.12,80.8 170.17,79.84 A11.V2 | v176.52,100.48 177.47,101.43 177.47,122.07 176.52,123.02 A11.D1
N$34  (via drill 0.61)
  Top 0.127: v96.82,112.55 97.78,113.5 102.22,113.5 102.86,112.86 110.47,112.86 v112.06,114.45
  Bottom 0.127: v96.82,112.55 96.82,111.91 95.55,110.64 95.55,107.47 96.19,106.83 96.19,104.29 95.55,103.66 95.55,90.32 96.5,89.37 A17.S2 | v112.06,114.45 112.38,114.77 112.38,116.67 A16.F1
N$35  (via drill 0.61)
  Top 0.127: A11.H1 180.01,114.45 180.96,115.4 186.68,115.4 187.63,114.45 191.44,114.45 A10.H1 192.71,113.82 193.66,113.82 194.61,112.86 206.68,112.86 v207,113.18
  Bottom 0.127: v207,113.18 207,112.23 207.63,111.59 A08.J2
N$36  (via drill 0.61)
  Top 0.127: v177.15,80.48 158.74,80.48 157.78,79.53 A12.V2
  Bottom 0.127: v177.15,80.48 178.1,81.43 178.1,89.37 180.96,92.23 180.96,100.16 182.23,101.43 182.23,103.97 A10.L2
N$37  (via drill 0.61)
  Top 0.127: v184.14,123.34 188.26,123.34 A10.D1
  Bottom 0.127: v184.14,123.34 184.14,112.86 182.87,111.59 A10.J2
N$38  (via drill 0.61)
  Top 0.127: v193.34,112.86 187.31,112.86 186.36,113.82 A10.H2
  Bottom 0.127: A09.T2 194.93,86.19 193.34,87.78 v193.34,112.86 193.34,125.25 192.39,126.2 A10.C1
N$39  (via drill 0.61)
  Top 0.127: v137.15,114.45 135.56,112.86 117.46,112.86 116.51,113.82 A16.H1 | v140,123.02 140.64,122.39 171.44,122.39 172.71,123.66 174.61,123.66 175.88,122.39 176.52,122.39 v178.1,123.98
  Bottom 0.127: v137.15,114.45 140,117.31 v140,123.02 | v178.1,123.98 182.23,119.85 182.23,117.94 A10.F2
N$40  (via drill 0.61)
  Top 0.127: v159.05,146.2 v180.33,146.2
  Bottom 0.127: 99.68,125.56 99.68,129.38 A17.B1 | 99.68,125.56 99.68,124.29 A17.D1 | v180.33,146.2 190.17,136.36 190.17,118.9 189.22,117.94 A10.F1 | v159.05,146.2 119.05,146.2 119.05,144.93 99.68,125.56
N$41  (via drill 0.61)
  Top 0.127: v100.31,96.67 98.73,96.67 97.46,95.4 A17.P2
  Bottom 0.127: v100.31,96.67 101.27,97.62 101.27,115.72 100.31,116.67 A17.F1
N$42  (via drill 0.61)
  Top 0.127: v122.86,145.25 123.81,146.2 157.78,146.2 158.74,145.25 186.68,145.25 187.31,145.89 189.22,145.89 190.17,144.93 v200.96,144.93
  Bottom 0.127: v122.86,145.25 122.86,144.62 105.39,127.15 103.81,127.15 A17.C1 | v200.96,144.93 204.46,141.44 204.46,133.82 A09.A1
N$43  (via drill 0.61)
  Top 0.127: v191.12,92.23 189.53,90.64 184.14,90.64 183.18,91.59 A10.R2
  Bottom 0.127: v191.12,92.23 190.8,92.54 190.8,103.66 191.76,104.61 191.76,107.15 A10.K1
N$44
  Bottom 0.127: 186.99,93.5 186.99,77.94 195.57,77.94 196.52,78.89 196.52,80.16 198.11,81.75 A09.U2 | 186.99,93.5 186.04,94.45 A10.P2 | 186.99,93.5 186.99,108.74 188.58,110.32 A10.J1
N$45  (via drill 0.61)
  Top 0.127: v175.56,113.5 175.25,113.82 173.66,113.82 A11.H2 | v180.96,102.07 181.6,102.7 190.49,102.7 191.44,101.75 A10.M1 | v180.96,110.96 176.83,110.96 A11.J1
  Bottom 0.127: v175.56,113.5 175.56,111.91 175.88,111.59 A11.J1 | v180.96,102.07 v180.96,110.96
N$46  (via drill 0.61)
  Top 0.127: v104.76,113.82 108.89,113.82 A16.H2
  Bottom 0.127: v104.76,113.82 104.76,109.69 103.49,108.42 A17.K1
N$47  (via drill 0.61)
  Top 0.127: v178.1,122.71 178.42,122.39 196.52,122.39 v201.28,127.15
  Bottom 0.127: v178.1,122.71 178.1,109.37 179.06,108.42 A11.K1 | v201.28,127.15 201.28,129.38 A09.B1
N$48  (via drill 0.61)
  Top 0.127: v173.66,104.93 175.56,104.93 A11.L1
  Bottom 0.127: v173.66,104.93 173.66,106.83 173.34,107.15 A11.K2
N$49  (via drill 0.61)
  Top 0.127: v179.69,92.23 181.6,90.32 197.79,90.32 199.38,91.91 200.01,91.91 201.28,90.64 209.22,90.64 v210.81,92.23
  Bottom 0.127: v179.69,92.23 180.64,93.18 180.64,98.26 176.83,98.26 A11.N1 | v210.81,92.23 210.81,94.45 A08.P2
N$50  (via drill 0.61)
  Top 0.127: v207.63,94.13 207.31,93.81 182.87,93.81 182.87,97.62 A10.N2
  Bottom 0.127: v207.63,94.13 207.63,92.54 A08.R2
N$51
  Bottom 0.127: A09.V1 201.92,78.57 202.23,78.26 202.23,77.3 203.82,75.72 212.08,75.72 212.08,79.53 212.39,79.84 212.39,106.2 211.44,107.15 A08.K2
N$52  (via drill 0.61)
  Top 0.127: v208.58,101.75 210.49,101.75 A08.M2 | v209.22,124.61 208.9,124.93 203.19,124.93 202.23,123.98 A09.D1
  Bottom 0.127: v208.58,101.75 209.22,102.39 v209.22,124.61
N$53  (via drill 0.61)
  Top 0.127: v174.29,74.45 161.28,74.45 160.96,74.77 134.92,74.77 132.7,72.54 v110.47,72.54
  Bottom 0.127: v174.29,74.45 184.45,84.61 184.45,87.15 185.41,88.1 A10.S2 | v110.47,72.54 104.44,78.57 104.44,96.99 102.86,98.58 102.86,99.53 105.08,101.75 105.08,106.83 106.03,107.78 106.03,110.32 A16.J2
N$54  (via drill 0.61)
  Top 0.127: v113.65,96.67 105.08,96.67 103.81,95.4 A17.P1 | v179.06,97.31 181.28,99.53 187.31,99.53 188.26,98.58 A10.N1 | v170.17,75.72 169.53,76.35 135.24,76.35 133.97,75.08 123.81,75.08 122.54,73.81 120.64,73.81 v119.68,74.77
  Bottom 0.127: A16.E1 115.55,119.85 113.97,118.26 113.97,96.99 v113.65,96.67 113.97,96.35 114.28,96.04 114.28,82.38 114.92,81.75 114.92,79.53 v119.68,74.77 | v179.06,97.31 177.47,95.72 177.47,83.02 v170.17,75.72
N$55
  Top 0.127: A08.N2 208.58,98.58 209.85,99.85 242.87,99.85 252.08,90.64 257.16,90.64 258.11,91.59 A04.R2
N$56  (via drill 0.61)
  Top 0.127: v208.27,83.65 249.54,83.65 251.13,82.07 251.13,77.94 253.67,77.94 v258.43,82.7
  Bottom 0.127: v208.27,83.65 206.68,85.24 206.68,103.02 207.63,103.97 A08.L2 | v258.43,82.7 261.61,85.88 261.61,88.1 A04.S2
N$57
  Top 0.127: A10.V2 183.18,79.53 184.14,80.48 193.66,80.48 194.61,79.53 A09.V2
  Bottom 0.127: A10.P1 192.07,94.45 192.07,90.32 190.8,89.05 190.8,85.24 194.93,81.11 194.93,79.84 A09.V2
N$58
  Bottom 0.127: A10.V1 188.58,79.84 187.63,80.8 187.63,90.32 188.58,91.27 A10.R1
N$59  (via drill 0.61)
  Top 0.127: v185.09,76.35 184.45,76.99 134.61,76.99 133.34,75.72 v113.33,75.72 | v111.11,103.97 111.75,103.34 113.65,103.34 v115.24,104.93
  Bottom 0.127: v185.09,76.35 185.09,81.43 185.41,81.75 A10.U2 | v113.33,75.72 111.11,77.94 v111.11,103.97 | v115.24,104.93 115.55,105.24 115.55,107.15 A16.K1
N$60  (via drill 0.61)
  Top 0.127: v122.54,84.61 123.17,83.97 185.72,83.97 186.99,82.7 191.44,82.7 A10.U1 | v121.59,91.27 120.95,90.64 101.58,90.64 100.63,91.59 A17.R1
  Bottom 0.127: v122.54,84.61 120.95,86.19 120.95,90.64 v121.59,91.27 | A17.T2 93.33,84.92 92.38,83.97 92.38,78.89 93.33,77.94 98.73,77.94 98.73,90.32 99.68,91.27 A17.R1
N$61  (1 unrouted)
  Bottom 0.127: R2.1 133.65,161.44 133.65,158.9 S4.3
N$62  (via drill 0.61)
  Top 0.127: v95.23,104.61 99.36,104.61 A17.L1
  Bottom 0.127: v95.23,104.61 95.23,81.11 93.97,79.84 A17.V2
N$63  (via drill 0.61)
  Top 0.127: v103.81,98.89 100.95,98.89 100.63,98.58 A17.N1 | v108.57,110.32 108.89,110.64 112.06,110.64 A16.J1
  Bottom 0.127: v103.81,98.89 107.94,103.02 107.94,109.69 v108.57,110.32
N$64  (1 unrouted)
  Top 0.127: R1.1 126.03,161.44 126.03,158.9 S4.1
N$65  (via drill 0.61)
  Top 0.127: v124.13,145.25 124.76,145.89 157.47,145.89 158.42,144.93 v187.63,144.93
  Bottom 0.127: v124.13,145.25 98.41,119.53 98.41,116.67 99.05,116.04 99.05,112.23 98.73,111.91 98.73,96.99 101.27,94.45 101.27,90.96 102.86,89.37 A17.S1 | v187.63,144.93 189.85,147.16 200.01,147.16 200.01,135.09 204.46,130.65 204.46,127.47 A09.C1
N$66
  Bottom 0.127: A21.L1 49.52,105.24 51.1,106.83 51.1,120.8 61.58,131.28 64.75,131.28 64.75,127.47 A20.C1
N$67
  Bottom 0.127: A21.U2 46.34,83.02 47.93,84.61 47.93,89.05 60.63,101.75 60.63,109.37 61.58,110.32 A20.J1
N$68
  Top 0.127: R7.1 156.51,162.08 158.1,162.08 D1.A 158.42,160.81 158.42,159.86 C5.-
N$69  (via drill 0.61)
  Top 0.127: v53.96,110.96 55.87,112.86 63.48,112.86 64.44,113.82 A20.H1
  Bottom 0.127: v53.96,110.96 53.96,109.69 52.69,108.42 A21.K1
N$70
  Bottom 0.127: A21.V2 43.16,79.84 44.75,81.43 44.75,89.37 60.31,104.93 60.31,121.75 61.58,123.02 A20.D1
N$71
  Top 0.127: R1.2 126.67,172.24 133.02,172.24 R2.2 134.29,172.24 138.73,172.24 R4.2 140,172.24 144.45,172.24 R5.2 145.72,172.24 148.26,172.24 C3.1 149.53,172.24 152.07,172.24 R6.2 153.34,172.24 154.93,173.83 178.42,173.83 180.01,172.24 R8.2 181.28,172.24 183.5,172.24 R3.1
N$72
  Top 0.127: R6.1 152.7,161.44 152.7,158.9 S3.3 154.29,153.82 156.51,153.82 157.15,153.19 C4.-
SKIP_L  (via drill 0.61)
  Top 0.127: v273.99,80.48 264.15,80.48 262.56,82.07 A04.U2
  Bottom 0.127: 273.35,81.11 v273.99,80.48 | 273.35,81.11 273.35,106.2 274.31,107.15 A03.K2 | 273.35,81.11 273.35,56.35 273.04,56.03 273.04,39.84 274.31,38.57 B03.K2
VCC  (1 unrouted)
  Top 0.203: B18.A2 84.76,63.65 85.71,64.6 120.64,64.6 121.59,63.65 B15.A2 122.86,63.65 124.13,64.92 171.12,64.92 172.39,63.65 B11.A2 173.66,63.65 174.61,64.6 196.84,64.6 | 196.84,64.6 197.79,63.65 B09.A2 | 209.54,64.6 210.49,63.65 B08.A2 | 196.84,64.6 209.54,64.6 | 222.24,64.6 223.19,63.65 B07.A2 | 209.54,64.6 222.24,64.6 | 222.24,64.6 234.94,64.6 235.89,63.65 B06.A2 | 44.44,134.46 34.91,134.46 33.96,133.5 A22.A2 | 44.44,134.46 45.39,133.5 A21.A2 | 57.13,134.46 58.09,133.5 A20.A2 | 57.13,134.46 44.44,134.46 | 69.83,134.46 70.79,133.5 A19.A2 | 69.83,134.46 57.13,134.46 | 69.83,134.46 82.53,134.46 83.49,133.5 A18.A2 84.76,132.87 85.71,131.92 95.23,131.92 96.19,132.87 A17.A2 97.46,133.5 98.73,134.77 107.62,134.77 108.89,133.5 A16.A2 110.16,133.5 111.11,134.46 120.64,134.46 | 234.94,134.46 225.41,134.46 224.46,133.5 A07.A2 223.19,133.5 221.92,134.77 213.03,134.77 211.76,133.5 A08.A2 210.49,133.5 209.54,134.46 196.84,134.46 | 234.94,134.46 235.89,133.5 A06.A2 | 247.64,134.46 248.59,133.5 A05.A2 | 234.94,134.46 247.64,134.46 | 247.64,134.46 260.34,134.46 261.29,133.5 A04.A2 | 120.64,134.46 121.59,133.5 A15.A2 | 133.34,134.46 134.29,133.5 A14.A2 | 120.64,134.46 133.34,134.46 | 146.04,134.46 146.99,133.5 A13.A2 | 133.34,134.46 146.04,134.46 | 158.74,134.46 159.69,133.5 A12.A2 | 146.04,134.46 158.74,134.46 | 171.44,134.46 172.39,133.5 A11.A2 | 158.74,134.46 171.44,134.46 | 184.14,134.46 185.09,133.5 A10.A2 | 171.44,134.46 184.14,134.46 | 196.84,134.46 197.79,133.5 A09.A2 | 184.14,134.46 196.84,134.46
  Bottom 0.203: B18.A2 83.8,63.97 79.36,68.41 79.36,94.77 79.04,95.08 79.04,126.2 83.8,130.96 83.8,132.55 A18.A2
